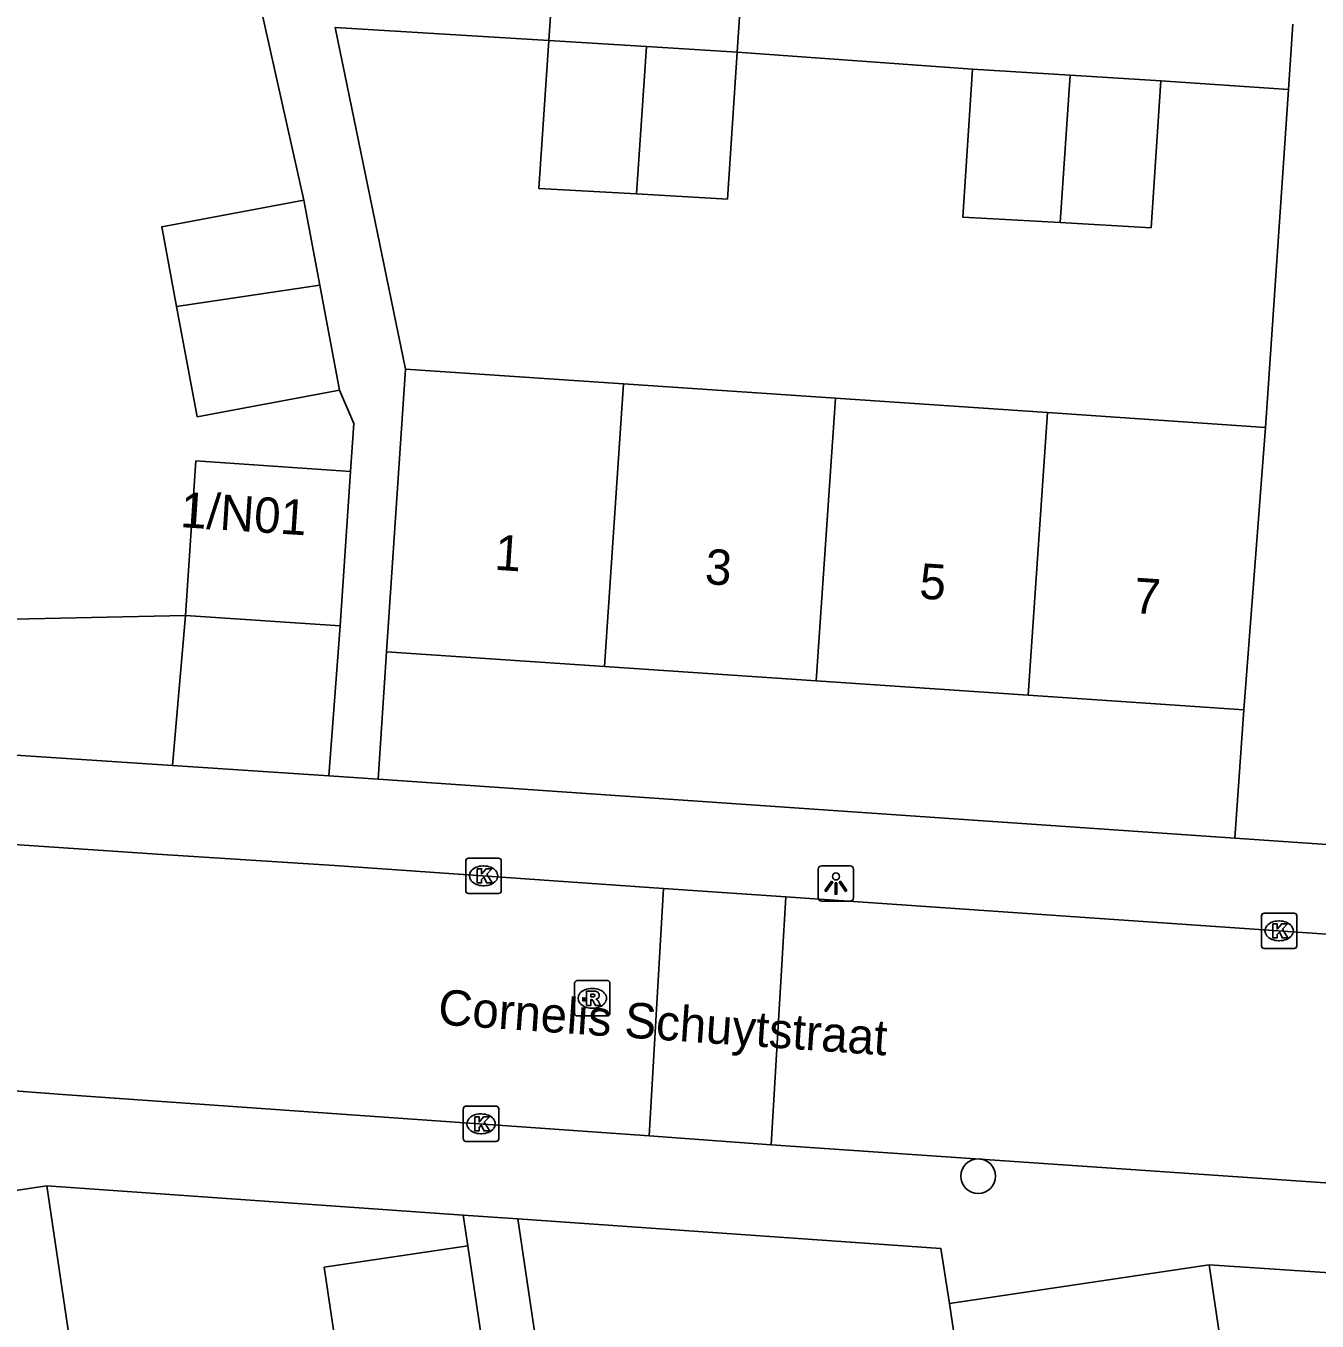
# Model space of a CAD drawing. Extents: x 159053 to 160041, y 380450 to 381422.
# Drawn here: x 159326.36 to 159362.85, y 381120.16 to 381156.77 of the extents above; entities that cross this region are included whole.
import ezdxf

# ---------------------------------------------------------------- set-up
doc = ezdxf.new("R2010")
doc.units = 0
for name, color, linetype in [('IMGEO_Boom', 7, 'Continuous'), ('IMGEO_Groenvoorziening', 7, 'Continuous'), ('IMGEO_Kolk', 7, 'Continuous'), ('IMGEO_Lichtpunt', 7, 'Continuous'), ('IMGEO_Muur', 7, 'Continuous'), ('IMGEO_Openbare_ruimte_label', 7, 'Continuous'), ('IMGEO_Pand', 7, 'Continuous'), ('IMGEO_Pand_nummerreeks', 7, 'Continuous'), ('IMGEO_Rijbaan_lokaal_open', 7, 'Continuous'), ('IMGEO_Rioolput', 7, 'Continuous'), ('IMGEO_Voetpad_open', 7, 'Continuous')]:
    doc.layers.add(name, color=color, linetype=linetype)

msp = doc.modelspace()

# ---------------------------------------------------------------- linework, layer by layer
at = {"layer": 'IMGEO_Boom'}
msp.add_circle((159353.275, 381124.256), 0.489, dxfattribs=at)
at = {"layer": 'IMGEO_Groenvoorziening'}
for points in [[(159324.333, 381141.685), (159324.851, 381141.762), (159325.116, 381139.979), (159330.87, 381140.103)], [(159330.511, 381135.86), (159330.649, 381137.491), (159330.87, 381140.103)]]:
    msp.add_lwpolyline(points, dxfattribs=at)
at = {"layer": 'IMGEO_Kolk'}
for p, q in [((159338.795, 381132.318), (159338.795, 381133.17)), ((159338.87, 381133.244), (159339.722, 381133.244)), ((159339.283, 381133.024), (159339.308, 381133.024)), ((159339.796, 381133.17), (159339.796, 381132.318)), ((159339.722, 381132.244), (159338.87, 381132.244)), ((159339.306, 381132.464), (159339.281, 381132.464)), ((159361.278, 381130.764), (159361.278, 381131.616)), ((159361.353, 381131.69), (159362.205, 381131.69)), ((159362.279, 381131.616), (159362.279, 381130.764)), ((159361.766, 381131.47), (159361.791, 381131.47)), ((159361.789, 381130.91), (159361.764, 381130.91)), ((159362.205, 381130.69), (159361.353, 381130.69)), ((159338.725, 381125.309), (159338.725, 381126.161)), ((159338.8, 381126.235), (159339.652, 381126.235)), ((159339.213, 381126.015), (159339.238, 381126.015)), ((159339.726, 381126.161), (159339.726, 381125.309)), ((159339.236, 381125.455), (159339.211, 381125.455)), ((159339.652, 381125.235), (159338.8, 381125.235))]:
    msp.add_line(p, q, dxfattribs=at)
for points in [[(159338.795, 381132.318), (159338.795, 381133.17)], [(159338.87, 381133.244), (159339.722, 381133.244)], [(159339.796, 381133.17), (159339.796, 381132.318)], [(159339.116, 381132.944), (159339.239, 381132.944), (159339.239, 381132.793), (159339.369, 381132.944), (159339.533, 381132.944), (159339.387, 381132.793), (159339.54, 381132.544), (159339.388, 381132.544), (159339.303, 381132.708), (159339.239, 381132.641), (159339.239, 381132.544), (159339.116, 381132.544), (159339.116, 381132.944)], [(159339.722, 381132.244), (159338.87, 381132.244)], [(159361.278, 381130.764), (159361.278, 381131.616)], [(159361.353, 381131.69), (159362.205, 381131.69)], [(159362.279, 381131.616), (159362.279, 381130.764)], [(159361.599, 381131.39), (159361.722, 381131.39), (159361.722, 381131.239), (159361.852, 381131.39), (159362.016, 381131.39), (159361.87, 381131.239), (159362.023, 381130.99), (159361.871, 381130.99), (159361.786, 381131.154), (159361.722, 381131.087), (159361.722, 381130.99), (159361.599, 381130.99), (159361.599, 381131.39)], [(159362.205, 381130.69), (159361.353, 381130.69)], [(159338.725, 381125.309), (159338.725, 381126.161)], [(159338.8, 381126.235), (159339.652, 381126.235)], [(159339.726, 381126.161), (159339.726, 381125.309)], [(159339.046, 381125.935), (159339.169, 381125.935), (159339.169, 381125.784), (159339.299, 381125.935), (159339.463, 381125.935), (159339.317, 381125.784), (159339.47, 381125.535), (159339.318, 381125.535), (159339.233, 381125.699), (159339.169, 381125.632), (159339.169, 381125.535), (159339.046, 381125.535), (159339.046, 381125.935)], [(159339.652, 381125.235), (159338.8, 381125.235)]]:
    msp.add_lwpolyline(points, dxfattribs=at)
for centre, start, end in [((159338.872, 381133.168), 91.552, 178.448), ((159338.872, 381133.168), 91.552, 178.448), ((159339.72, 381133.168), 1.552, 88.448), ((159339.72, 381133.168), 1.552, 88.448), ((159338.872, 381132.32), 181.552, 268.448), ((159338.872, 381132.32), 181.552, 268.448), ((159339.72, 381132.32), 271.552, 358.448), ((159339.72, 381132.32), 271.552, 358.448), ((159361.355, 381131.614), 91.552, 178.448), ((159361.355, 381131.614), 91.552, 178.448), ((159362.203, 381131.614), 1.552, 88.448), ((159362.203, 381131.614), 1.552, 88.448), ((159361.355, 381130.766), 181.552, 268.448), ((159361.355, 381130.766), 181.552, 268.448), ((159362.203, 381130.766), 271.552, 358.448), ((159362.203, 381130.766), 271.552, 358.448), ((159338.802, 381126.159), 91.552, 178.448), ((159338.802, 381126.159), 91.552, 178.448), ((159339.65, 381126.159), 1.552, 88.448), ((159339.65, 381126.159), 1.552, 88.448), ((159338.802, 381125.311), 181.552, 268.448), ((159338.802, 381125.311), 181.552, 268.448), ((159339.65, 381125.311), 271.552, 358.448), ((159339.65, 381125.311), 271.552, 358.448)]:
    msp.add_arc(centre, 0.0765, start, end, dxfattribs=at)
for centre, major_axis, ratio, start_param, end_param in [((159339.282, 381132.744), (-0.387, 0.002), 0.722429, 4.712389, 7.853982), ((159339.307, 381132.744), (-0.39, 0.002), 0.717154, 1.570796, 4.712389), ((159361.765, 381131.19), (-0.387, 0.002), 0.722429, 4.712389, 7.853982), ((159361.79, 381131.19), (-0.39, 0.002), 0.717154, 1.570796, 4.712389), ((159339.212, 381125.735), (-0.387, 0.002), 0.722429, 4.712389, 7.853982), ((159339.237, 381125.735), (-0.39, 0.002), 0.717154, 1.570796, 4.712389)]:
    msp.add_ellipse(centre, major_axis=major_axis, ratio=ratio, start_param=start_param, end_param=end_param, dxfattribs=at)
at = {"layer": 'IMGEO_Lichtpunt'}
for p, q in [((159349.657, 381133.024), (159348.849, 381133.024)), ((159349.657, 381133.024), (159348.849, 381133.024)), ((159348.755, 381132.929), (159348.755, 381132.122)), ((159348.755, 381132.929), (159348.755, 381132.122)), ((159349.751, 381132.122), (159349.751, 381132.929)), ((159349.751, 381132.122), (159349.751, 381132.929)), ((159348.849, 381132.028), (159349.657, 381132.028)), ((159348.849, 381132.028), (159349.657, 381132.028))]:
    msp.add_line(p, q, dxfattribs=at)
for points in [[(159349.129, 381132.593), (159349.168, 381132.565), (159348.98, 381132.303), (159348.942, 381132.33), (159349.129, 381132.593)], [(159349.341, 381132.565), (159349.379, 381132.592), (159349.566, 381132.33), (159349.527, 381132.302), (159349.341, 381132.565)], [(159349.231, 381132.545), (159349.278, 381132.545), (159349.278, 381132.223), (159349.231, 381132.223), (159349.231, 381132.545)]]:
    msp.add_lwpolyline(points, dxfattribs=at)
msp.add_circle((159349.254, 381132.727), 0.0994, dxfattribs=at)
for centre, start, end in [((159348.849, 381132.929), 90, 180), ((159348.849, 381132.929), 90, 180), ((159349.657, 381132.929), 0, 90), ((159349.657, 381132.929), 0, 90), ((159348.849, 381132.122), 180, 270), ((159348.849, 381132.122), 180, 270), ((159349.657, 381132.122), 270, 0), ((159349.657, 381132.122), 270, 360)]:
    msp.add_arc(centre, 0.0946, start, end, dxfattribs=at)
at = {"layer": 'IMGEO_Muur'}
for points in [[(159326.952, 381123.978), (159338.721, 381123.156)], [(159340.268, 381123.048), (159352.216, 381122.213), (159352.462, 381120.658)]]:
    msp.add_lwpolyline(points, dxfattribs=at)
at = {"layer": 'IMGEO_Pand'}
for points in [[(159343.619, 381152.02), (159340.863, 381152.177), (159341.14, 381156.354)], [(159341.14, 381156.354), (159343.902, 381156.186)], [(159343.902, 381156.186), (159343.619, 381152.02)], [(159343.619, 381152.02), (159346.187, 381151.873), (159346.463, 381156.031)], [(159343.902, 381156.186), (159346.463, 381156.031)], [(159353.113, 381155.543), (159352.836, 381151.366), (159355.592, 381151.209)], [(159353.113, 381155.543), (159355.875, 381155.375)], [(159355.592, 381151.209), (159355.875, 381155.375)], [(159355.875, 381155.375), (159358.436, 381155.22)], [(159358.436, 381155.22), (159358.16, 381151.062), (159355.592, 381151.209)], [(159330.623, 381148.839), (159330.201, 381151.091), (159334.222, 381151.845)], [(159334.222, 381151.845), (159334.673, 381149.439)], [(159334.673, 381149.439), (159330.623, 381148.839)], [(159334.673, 381149.439), (159335.229, 381146.475)], [(159335.229, 381146.475), (159331.208, 381145.721), (159330.623, 381148.839)], [(159337.094, 381147.067), (159336.552, 381139.079)], [(159343.255, 381146.649), (159337.094, 381147.067)], [(159343.255, 381146.649), (159342.713, 381138.661)], [(159349.242, 381146.244), (159343.255, 381146.649)], [(159348.7, 381138.256), (159349.242, 381146.244)], [(159355.228, 381145.838), (159349.242, 381146.244)], [(159355.228, 381145.838), (159354.686, 381137.85)], [(159361.392, 381145.42), (159355.228, 381145.838)], [(159361.392, 381145.42), (159360.782, 381137.437)], [(159330.87, 381140.103), (159331.166, 381144.471), (159335.537, 381144.175)], [(159335.537, 381144.175), (159335.241, 381139.807)], [(159330.87, 381140.103), (159335.241, 381139.807)], [(159336.552, 381139.079), (159342.713, 381138.661)], [(159342.713, 381138.661), (159348.7, 381138.256)], [(159348.7, 381138.256), (159354.686, 381137.85)], [(159354.686, 381137.85), (159360.782, 381137.437)], [(159326.952, 381123.978), (159319.552, 381122.881)], [(159327.858, 381117.868), (159326.952, 381123.978)], [(159335.2, 381118.957), (159334.796, 381121.68), (159338.851, 381122.282)], [(159338.851, 381122.282), (159339.255, 381119.559)], [(159359.798, 381121.745), (159352.462, 381120.658)], [(159360.696, 381115.69), (159359.798, 381121.745)], [(159352.462, 381120.658), (159353.36, 381114.602)]]:
    msp.add_lwpolyline(points, dxfattribs=at)
at = {"layer": 'IMGEO_Rijbaan_lokaal_open'}
for points in [[(159320.6, 381133.986), (159325.192, 381133.689), (159330.073, 381133.355), (159335.084, 381133.041), (159344.386, 381132.385)], [(159344.386, 381132.385), (159343.979, 381125.396)], [(159344.386, 381132.385), (159347.843, 381132.155)], [(159347.843, 381132.155), (159347.425, 381125.142)], [(159408.675, 381127.944), (159347.843, 381132.155)], [(159320.118, 381127.116), (159327.397, 381126.568), (159343.979, 381125.396)], [(159343.979, 381125.396), (159347.425, 381125.142)], [(159347.425, 381125.142), (159367.896, 381123.741)]]:
    msp.add_lwpolyline(points, dxfattribs=at)
at = {"layer": 'IMGEO_Rioolput'}
for p, q in [((159341.868, 381128.857), (159341.868, 381129.709)), ((159341.943, 381129.783), (159342.795, 381129.783)), ((159342.869, 381129.709), (159342.869, 381128.857)), ((159342.356, 381129.563), (159342.381, 381129.563)), ((159342.379, 381129.003), (159342.354, 381129.003)), ((159342.795, 381128.783), (159341.943, 381128.783))]:
    msp.add_line(p, q, dxfattribs=at)
for points in [[(159341.868, 381128.857), (159341.868, 381129.709)], [(159341.943, 381129.783), (159342.795, 381129.783)], [(159342.869, 381129.709), (159342.869, 381128.857)], [(159342.457, 381129.481), (159342.205, 381129.483), (159342.205, 381129.083)], [(159342.383, 381129.402), (159342.329, 381129.402), (159342.329, 381129.321)], [(159342.329, 381129.321), (159342.381, 381129.321)], [(159342.205, 381129.083), (159342.329, 381129.083), (159342.329, 381129.245), (159342.34, 381129.245)], [(159342.387, 381129.216), (159342.458, 381129.083), (159342.598, 381129.083), (159342.533, 381129.209)], [(159342.795, 381128.783), (159341.943, 381128.783)]]:
    msp.add_lwpolyline(points, dxfattribs=at)
for centre, radius, start, end in [((159341.945, 381129.707), 0.0765, 91.552, 178.448), ((159341.945, 381129.707), 0.0765, 91.552, 178.448), ((159342.793, 381129.707), 0.0765, 1.552, 88.448), ((159342.793, 381129.707), 0.0765, 1.552, 88.448), ((159342.365, 381129.51), 0.19, 274.7715, 282.9687), ((159342.389, 381129.306), 0.0964, 77.0061, 93.1865), ((159342.403, 381129.363), 0.0378, 276.6634, 79.6772), ((159342.456, 381129.371), 0.109, 350.3612, 89.416), ((159342.454, 381129.371), 0.112, 277.5842, 350.9817), ((159342.339, 381129.192), 0.0533, 26.0293, 88.6989), ((159342.438, 381129.156), 0.108, 29.5134, 73.7905), ((159341.945, 381128.859), 0.0765, 181.552, 268.448), ((159341.945, 381128.859), 0.0765, 181.552, 268.448), ((159342.793, 381128.859), 0.0765, 271.552, 358.448), ((159342.793, 381128.859), 0.0765, 271.552, 358.448)]:
    msp.add_arc(centre, radius, start, end, dxfattribs=at)
for centre, major_axis, ratio, start_param, end_param in [((159342.355, 381129.283), (-0.387, 0.002), 0.722429, 4.712389, 7.853982), ((159342.38, 381129.283), (-0.39, 0.002), 0.717154, 1.570796, 4.712389)]:
    msp.add_ellipse(centre, major_axis=major_axis, ratio=ratio, start_param=start_param, end_param=end_param, dxfattribs=at)
at = {"layer": 'IMGEO_Voetpad_open'}
for points in [[(159341.14, 381156.354), (159341.242, 381157.891), (159334.797, 381158.146), (159334.516, 381159.476)], [(159334.222, 381151.845), (159332.778, 381158.297)], [(159346.589, 381157.879), (159346.463, 381156.031)], [(159362.169, 381156.817), (159362.043, 381154.974)], [(159337.094, 381147.067), (159335.099, 381156.721), (159341.14, 381156.354)], [(159346.463, 381156.031), (159353.113, 381155.543)], [(159358.436, 381155.22), (159362.043, 381154.974)], [(159362.043, 381154.974), (159361.392, 381145.42)], [(159335.537, 381144.175), (159335.629, 381145.526), (159335.229, 381146.475)], [(159335.241, 381139.807), (159334.921, 381135.568)], [(159336.314, 381135.476), (159336.552, 381139.079)], [(159360.782, 381137.437), (159360.526, 381133.81)], [(159330.511, 381135.86), (159322.216, 381136.408), (159320.412, 381136.566)], [(159334.921, 381135.568), (159330.511, 381135.86)], [(159336.314, 381135.476), (159334.921, 381135.568)], [(159360.526, 381133.81), (159336.314, 381135.476)], [(159360.526, 381133.81), (159363.677, 381133.592)], [(159338.721, 381123.156), (159326.952, 381123.978)], [(159340.268, 381123.048), (159338.721, 381123.156)], [(159338.721, 381123.156), (159338.851, 381122.282)], [(159341.321, 381115.924), (159340.268, 381123.048)], [(159352.462, 381120.658), (159352.216, 381122.213), (159340.268, 381123.048)], [(159359.798, 381121.745), (159368.043, 381121.201)]]:
    msp.add_lwpolyline(points, dxfattribs=at)

# ---------------------------------------------------------------- texts
at = {"layer": 'IMGEO_Openbare_ruimte_label'}
msp.add_text('Cornelis Schuytstraat', height=1, rotation=356.045, dxfattribs=at).set_placement((159337.992, 381128.544))
at = {"layer": 'IMGEO_Pand_nummerreeks'}
for s, rotation, p in [('1/N01', 356.2155, (159330.71, 381142.603)), ('1', 356.1231, (159339.59, 381141.399)), ('3', 356.1231, (159345.533, 381140.997)), ('5', 356.1231, (159351.591, 381140.586)), ('7', 356.1231, (159357.648, 381140.176))]:
    msp.add_text(s, height=1, rotation=rotation, dxfattribs=at).set_placement(p)

doc.saveas('drawing.dxf')
